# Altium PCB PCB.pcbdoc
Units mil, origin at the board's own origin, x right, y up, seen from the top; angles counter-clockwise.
Board outline 4135 x 3135 mil, 2 copper layers (Top Layer, Bottom Layer); 52 components, 91 nets, 233 pads, 32 vias.
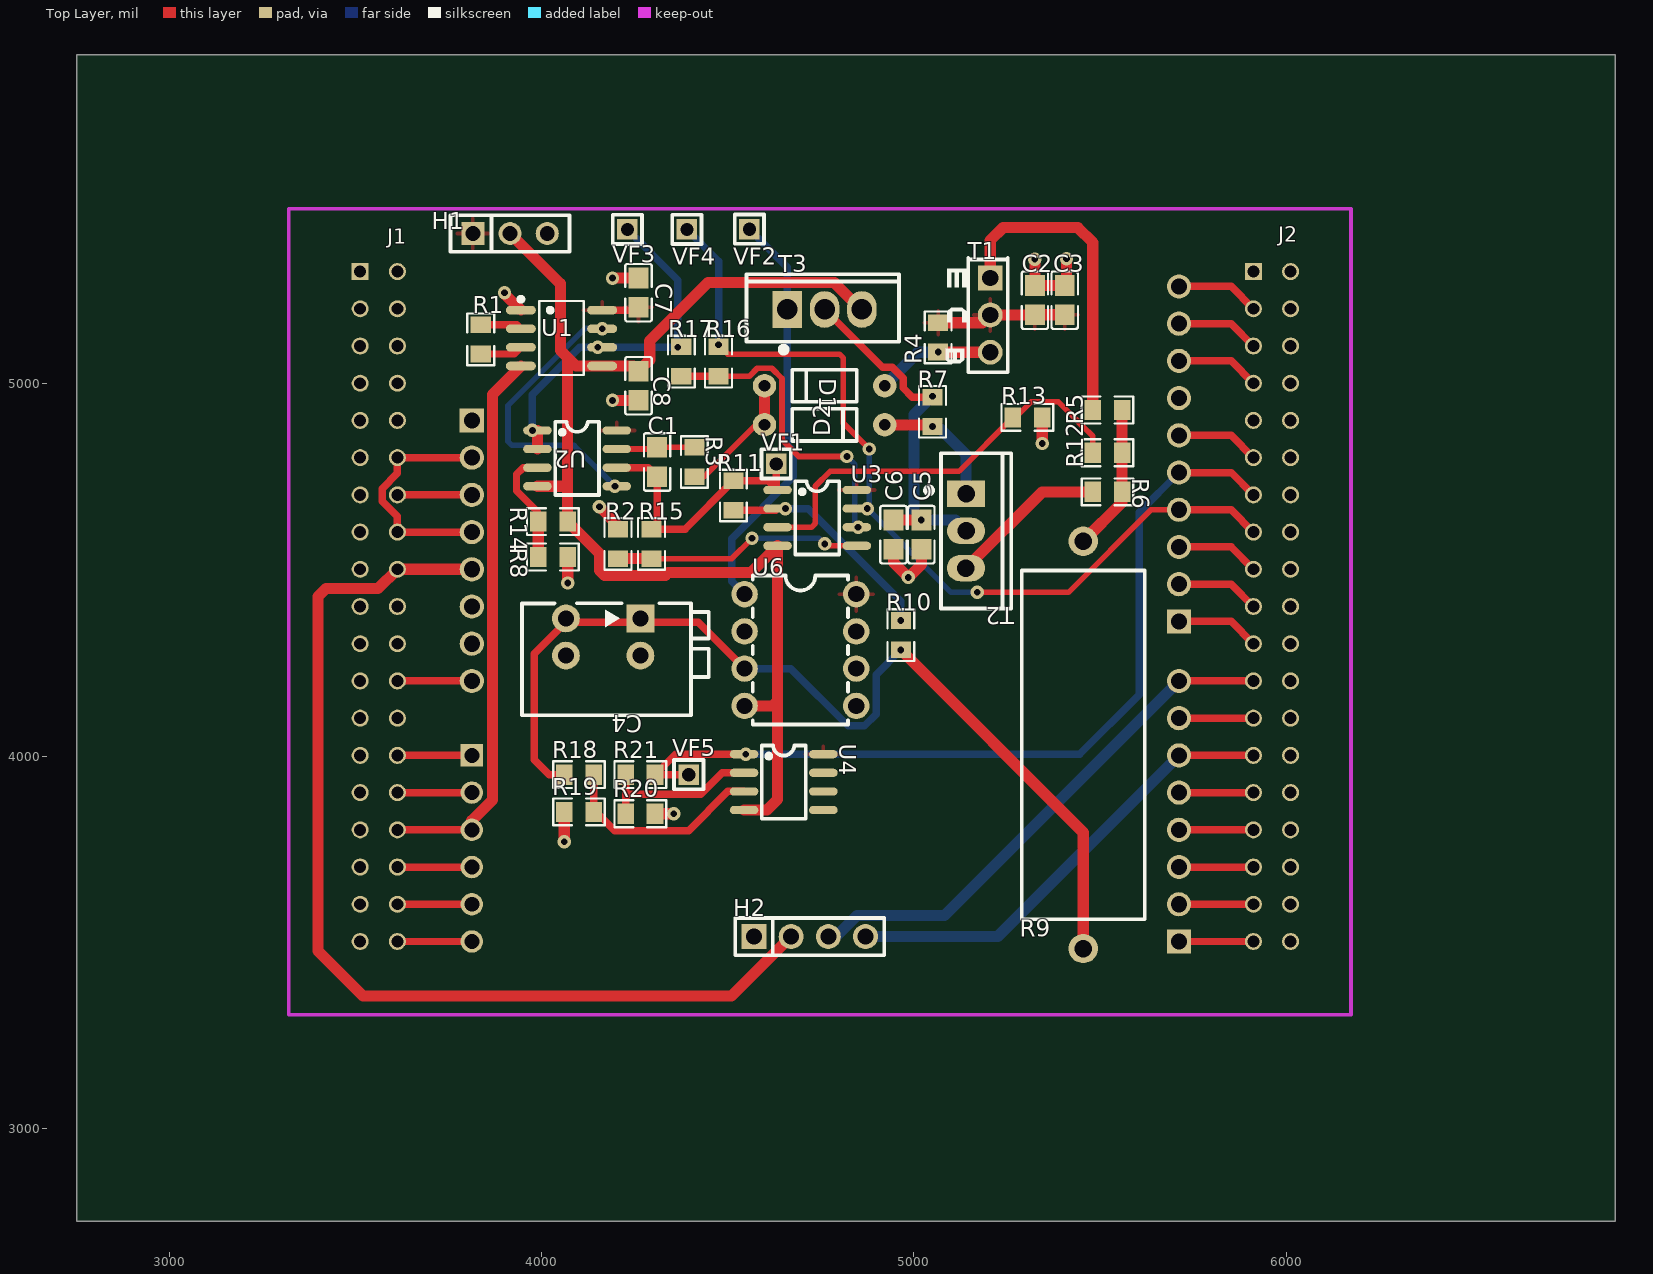
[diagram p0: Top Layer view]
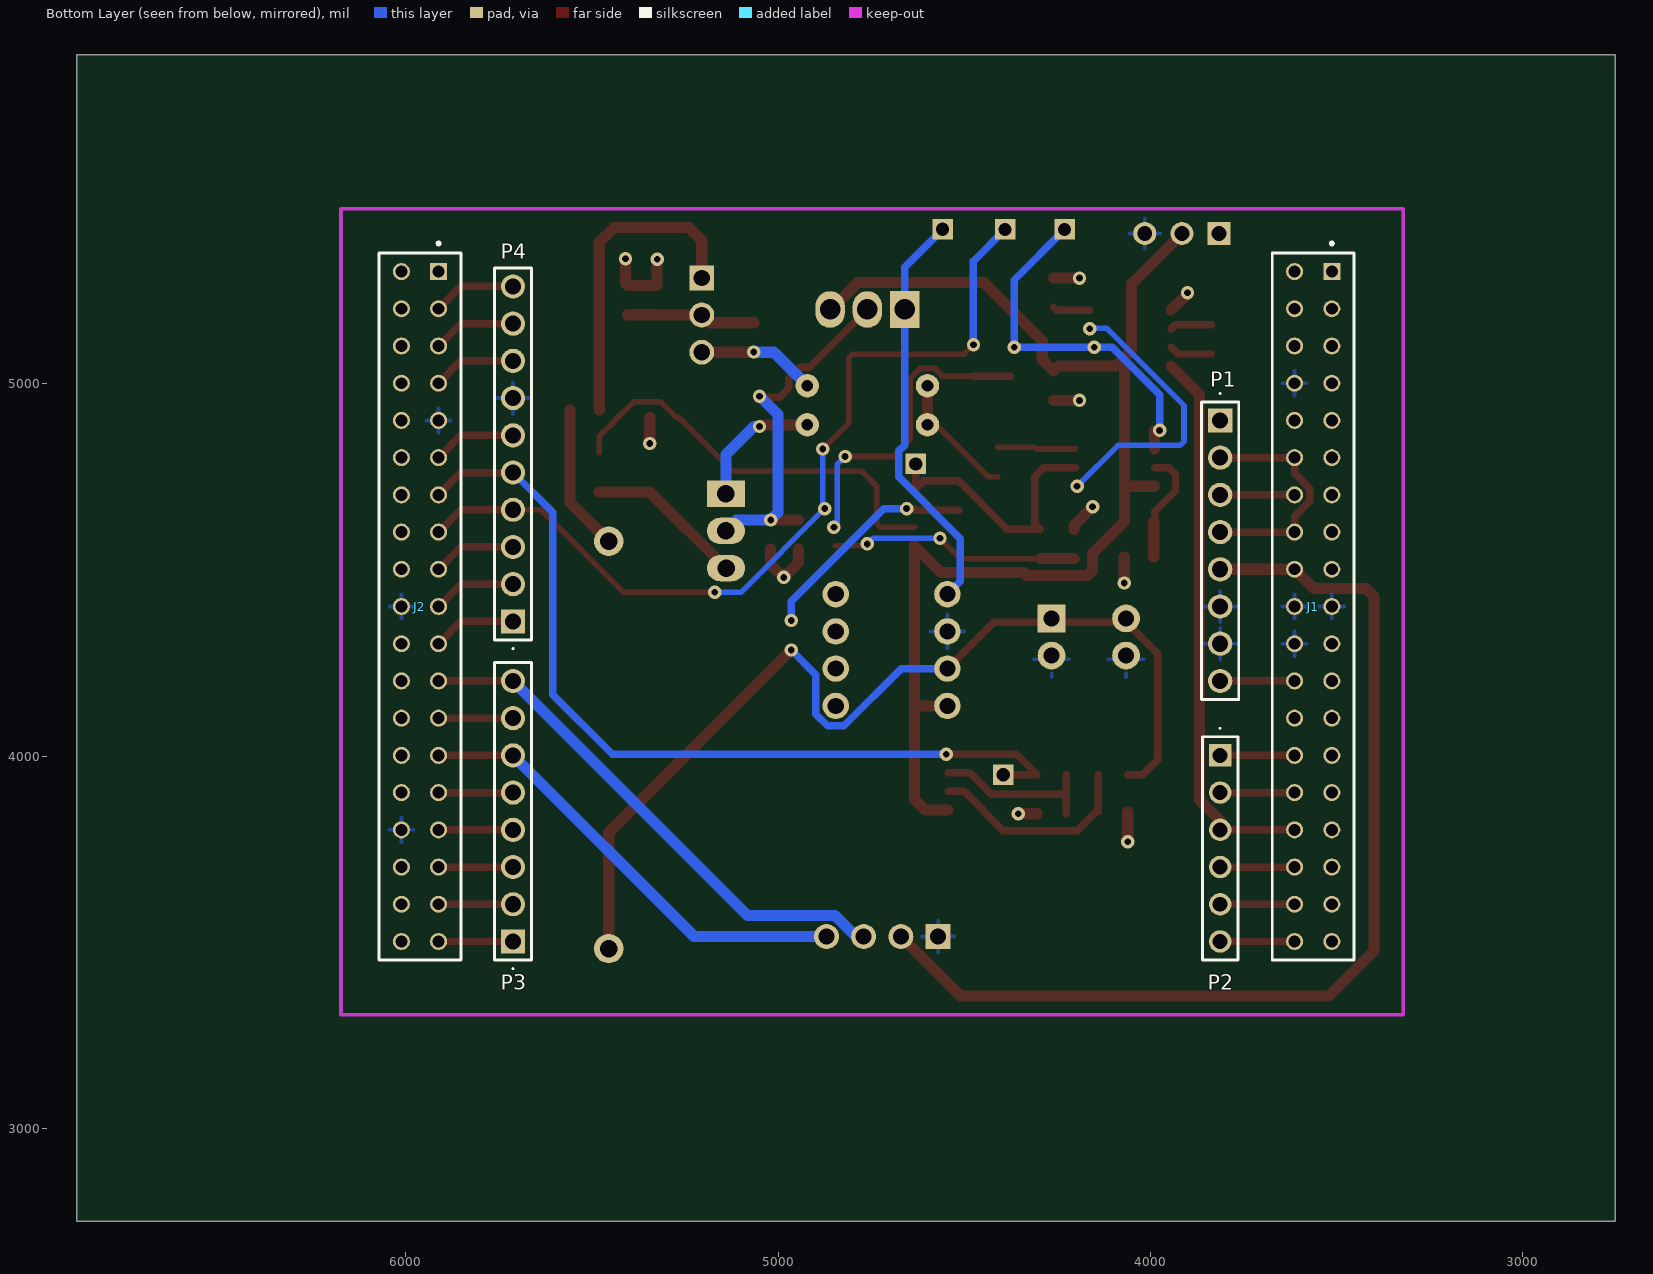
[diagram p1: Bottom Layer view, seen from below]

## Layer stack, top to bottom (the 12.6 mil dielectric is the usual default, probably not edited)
Top Layer: signal copper (thickness not stored)
Dielectric: dielectric 12.6, FR-4, Dk 4.8
Bottom Layer: signal copper (thickness not stored)

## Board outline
6885,2750 2750,2750 2750,5885 6885,5885

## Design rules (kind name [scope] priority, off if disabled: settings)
BoardOutlineClearance safeClearance [All] p0: genericclearance=10 ignorepadtopadclearanceinfootprint=FALSE except(0: Arc-SplitContinuation Track-SplitContinuation SMDPad-SplitContinuation THPad-SplitContinuation Via-SplitContinuation Fill-SplitContinuation Poly-SplitContinuation Region-SplitContinuation Text-SplitContinuation; 8: Track-CutoutEdge SMDPad-CutoutEdge THPad-CutoutEdge Via-CutoutEdge Fill-CutoutEdge Region-CutoutEdge; 11.8: Track-OutlineEdge SMDPad-OutlineEdge THPad-OutlineEdge Via-OutlineEdge Fill-OutlineEdge Region-OutlineEdge Poly-OutlineEdge Text-OutlineEdge)
Clearance safeClearance [(InNet('J1') OR InNet('J2') OR InNet('P1') OR InNet('P2') OR InNet('P3') OR InNet('P4') OR InNet('GND') OR InNet('$1N1763') OR InNet('$1N1673') OR InNet('+12V') OR InNet('$1N2775') OR InNet('$1N2265') OR InNet('-12V') OR InNet('$1N2115') OR InNet('$1N2185') OR InNet('$1N2209') OR InNet('$1N1175') OR InNet('$1N1180') OR InNet('$1N3065') OR InNet('$1N3052') OR InNet('$1N2342') OR InNet('$1N2346') OR InNet('$1N2351') OR InNet('$1N1817') OR InNet('$1N2781') OR InNet('$1N2770') OR InNet('$1N1423') OR InNet('$1N2552') OR InNet('$1N1419') OR InNet('PC10') OR InNet('PC11') OR InNet('PC12') OR InNet('PD2') OR InNet('VDD') OR InNet('E5V') OR InNet('BOOT0') OR InNet('PF6') OR InNet('PF7') OR InNet('+3V3') OR InNet('PA13') OR InNet('NRST') OR InNet('PA14') OR InNet('PA15') OR InNet('+5V') OR InNet('PB7') OR InNet('PC13') OR InNet('VIN') OR InNet('PC14') OR InNet('PC15') OR InNet('PA0') OR InNet('PH0') OR InNet('PA1') OR InNet('PH1') OR InNet('PA4') OR InNet('VBAT') OR InNet('PB0') OR InNet('PC2') OR InNet('PC1') OR InNet('PC3') OR InNet('PC0') OR InNet('PA8') OR InNet('PB10') OR InNet('PB4') OR InNet('PB5') OR InNet('PB3') OR InNet('PA10') OR InNet('PA2') OR InNet('PA3') OR InNet('PB8') OR InNet('PB9') OR InNet('AVDD') OR InNet('PA5') OR InNet('PB6') OR InNet('PC7') OR InNet('PA9') OR InNet('PC9') OR InNet('PC8') OR InNet('PC6') OR InNet('PC5') OR InNet('U5V') OR InNet('PD8') OR InNet('PA12') OR InNet('PA11') OR InNet('PB12') OR InNet('PB11') OR InNet('PB2') OR InNet('PB1') OR InNet('PB15') OR InNet('PB14') OR InNet('PB13') OR InNet('PC4') OR InNet('PF5') OR InNet('PF4') OR InNet('$1N5009') OR InNet('$1N5010') OR InNet('PA7') OR InNet('PA6'))] p1: gap=7 ignorepadtopadclearanceinfootprint=FALSE except(6.9: Track-Hole SMDPad-Hole THPad-Hole Via-Hole Fill-Hole Region-Hole Poly-Hole Text-Hole Sheet-Hole; 8: Track-Track Track-SMDPad SMDPad-SMDPad Track-THPad SMDPad-THPad THPad-THPad Track-Via SMDPad-Via THPad-Via Via-Via Track-Fill SMDPad-Fill THPad-Fill Via-Fill Fill-Fill Track-Region SMDPad-Region THPad-Region Via-Region Fill-Region Region-Region Track-Poly SMDPad-Poly THPad-Poly Via-Poly Fill-Poly Region-Poly Poly-Poly Track-Text SMDPad-Text THPad-Text Via-Text Fill-Text Region-Text Poly-Text Text-Text; 11.8: Track-Sheet SMDPad-Sheet THPad-Sheet Via-Sheet Fill-Sheet Region-Sheet Poly-Sheet Text-Sheet)
DiffPairsRouting differentialPair [All] p1: maxuncoupledlength=10 minlimit=6 maxlimit=6 mostfreqgap=6 toplayer_minwidth=5 toplayer_prefwidth=10 toplayer_maxwidth=100 bottomlayer_minwidth=5 bottomlayer_prefwidth=10 bottomlayer_maxwidth=100
PasteMaskExpansion pasteMaskExpansion [All] p1: expansion=0
PlaneConnect innerPlane [All] p1: planeconnectstyle=Relief reliefexpansion=20 reliefentries=4 reliefconductorwidth=10 reliefairgap=10
PolygonConnect copperRegion [All] p1: connectstyle=Relief reliefentries=4 reliefconductorwidth=10 polygonreliefangle="90 Angle" airgapwidth=10
RoutingVias viaSize [All] p1: viastyle="Through Hole" holewidth=12 minholewidth=11.8 maxholewidth=236.2 width=24 minwidth=19.7 maxwidth=393.7
SolderMaskExpansion solderMaskExpansion [All] p1: useseparateexpansions=TRUE expansion=2 expansionbottom=2
Width trackWidth [All] p1: maxlimit=100 minlimit=15 preferedwidth=15

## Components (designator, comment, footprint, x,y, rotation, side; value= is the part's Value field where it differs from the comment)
C1 "CAP_0805" C0805 4310,4790 r90 top
C2 "CAP_0805" C0805 5325,5225 r90 top
C3 "CAP_0805" C0805 5405,5225 r90 top
C4 "KF141V-2.54-2P" CONN-TH_2P-P2.54_KF141V-2.54-2P 4165,4320 r270 top
C5 "CAP_0805" C0805 5020,4595 r270 top
C6 "CAP_0805" C0805 4945,4595 r270 top
C7 "CAP_0805" C0805 4260,5245 r270 top
C8 "CAP_0805" C0805 4260,4995 r90 top
D1 "1N4448TR" DO-35_BD2.0-L4.2-P8.20-D0.5-RD 4760,4995 r0 top
D2 "1N4448TR" DO-35_BD2.0-L4.2-P8.20-D0.5-RD 4760,4890 r180 top
H1 "HDR-F_2.54_1x3P" HDR-TH_3P-P2.54-V-F 3914.84,5404.08 r0 top locked
H2 "PZ254V-11-04P" HDR-TH_4P-P2.54-V-M 4720,3515 r0 top locked
J1 "CES-119-02-T-D" SAMTEC_CES-119-02-T-D 3512.13,5301.85 r90 bottom locked
J2 "CES-119-02-T-D" SAMTEC_CES-119-02-T-D 5912.13,5301.85 r90 bottom locked
P1 "61300811121" HDRV8W64P0X254_1X8_2032X254X854P 3812.13,4901.85 r270 bottom locked
P2 "10129378-906001BLF" 10129378906001BLF 3812.13,4001.85 r270 bottom locked
P3 "61300811121" HDRV8W64P0X254_1X8_2032X254X854P 5712.13,3501.85 r90 bottom locked
P4 "TSW-110-07-G-S" HDRV10W64P0X254_1X10_2540X254X838P 5712.13,4361.85 r90 bottom locked
R1 "Res_0805" R0805 3836.07,5119.71 r90 top
R2 "Res_0805" R0805 4205,4570 r270 top
R3 "Res_0805" R0805 4410,4790 r90 top
R4 "Res_0805" R0805 5065,5125 r90 top
R5 "Res_0805" R0805 5520,4930 r180 top
R6 "Res_0805" R0805 5520,4710 r0 top
R7 "Res_0805" R0805 5050,4925 r270 top
R8 "Res_0805" R0805 4030,4535 r180 top
R9 "15FR100E-T" RES-TH_BD8.4-L23.8-P27.8-D1.0 5455,4030 r90 top
R10 "Res_0805" R0805 4965,4325 r270 top
R11 "Res_0805" R0805 4515,4700 r90 top
R12 "Res_0805" R0805 5520,4815 r180 top
R13 "Res_0805" R0805 5305,4910 r180 top
R14 "Res_0805" R0805 4030,4630 r0 top
R15 "Res_0805" R0805 4295,4570 r270 top
R16 "Res_0805" R0805 4475,5060 r90 top
R17 "Res_0805" R0805 4375,5060 r90 top
R18 "Res_0805" R0805 4100,3950 r0 top
R19 "Res_0805" R0805 4100,3850 r0 top
R20 "Res_0805" R0805 4265,3845 r0 top
R21 "Res_0805" R0805 4265,3950 r0 top
T1 "MJE182G" TO-225-3_L7.6-W2.8-P2.54-L 5205,5185 r270 top
T2 "TIP32AG" TO-220-3_L10.0-W4.5-P2.54-L 5140,4605 r270 top
T3 "IRL540NPBF-VB" TO-220AB-3_L10.4-W4.6-P2.54-L 4760,5200 r0 top
U1 "INA826AID" SOIC-8_L4.9-W3.9-P1.27-LS6.0-BL 4053.13,5123.13 r270 top
U2 "OPA2277UA/2K5" SOIC-8_L5.0-W4.0-P1.27-LS6.0-BL 4095,4800 r270 top
U3 "OPA2277UA/2K5" SOIC-8_L5.0-W4.0-P1.27-LS6.0-BL 4740,4640 r270 top
U4 "OPA2277UA/2K5" SOIC-8_L5.0-W4.0-P1.27-LS6.0-BL 4650,3930 r270 top
U6 "LM358AN/NOPB" PDIP-8_L10.2-W6.5-P2.54-LS7.6-BL 4695,4285 r270 top
VF1 "HDR-M_2.54_1x1P" HDR-TH_1P-V-M_XKB_X4611WV-01I-C28D40 4630,4785 r0 top
VF2 "HDR-M_2.54_1x1P" HDR-TH_1P-V-M_XKB_X4611WV-01I-C28D40 4557.96,5415.75 r0 top
VF3 "HDR-M_2.54_1x1P" HDR-TH_1P-V-M_XKB_X4611WV-01I-C28D40 4230,5415 r0 top
VF4 "HDR-M_2.54_1x1P" HDR-TH_1P-V-M_XKB_X4611WV-01I-C28D40 4390,5415 r0 top
VF5 "HDR-M_2.54_1x1P" HDR-TH_1P-V-M_XKB_X4611WV-01I-C28D40 4395,3950 r0 top

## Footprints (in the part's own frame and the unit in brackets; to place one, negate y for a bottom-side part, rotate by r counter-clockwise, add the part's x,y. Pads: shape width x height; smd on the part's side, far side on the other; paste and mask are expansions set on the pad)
10129378906001BLF [mm]
  rect 1.53x1.53 hole 1.02: 1(0,0)
  round 1.53 hole 1.02: 2(2.54,0) 3(5.08,0) 4(7.62,0) 5(10.16,0) 6(12.7,0)
  silkscreen extent -1.9,-1.2 13.97,1.2
C0805 [mm]
  rect 1.41x1.35 smd: 1(-1,0) 2(1,0)
  silkscreen extent -1.96,-0.9 1.96,0.9
CONN-TH_2P-P2.54_KF141V-2.54-2P [mm]
  rect 1.9x1.9 hole 1.1: 1(-1.27,2.54)
  round 1.9 hole 1.1 copper offset 0,0: 1(-1.27,-2.54) 2(1.27,2.54) 2(1.27,-2.54)
  silkscreen extent -2.3,-5.54 5.35,7.2
DO-35_BD2.0-L4.2-P8.20-D0.5-RD [mm]
  round 1.6 hole 0.8: 1(-4.1,0) 2(4.1,0)
  silkscreen extent -2.2,-1.1 2.2,1.1
HDR-TH_1P-V-M_XKB_X4611WV-01I-C28D40 [mm]
  rect 1.4x1.4 hole 0.9: 1(0,0)
  silkscreen extent -1,-1 1,1
HDR-TH_3P-P2.54-V-F [mil]
  rect 62x62 hole 40.16: 1(-100,0)
  round 62 hole 40.16: 2(0,0) 3(100,0)
  silkscreen extent -160,-49 160,49
HDR-TH_4P-P2.54-V-M [mm]
  rect 1.7x1.7 hole 1.1: 1(-3.81,0)
  round 1.7 hole 1.1: 2(-1.27,0) 3(1.27,0) 4(3.81,0)
  silkscreen extent -5.08,-1.27 5.08,1.27
HDRV8W64P0X254_1X8_2032X254X854P [mm]
  rect 1.65x1.65 hole 1.1: 1(0,0)
  round 1.65 hole 1.1: 2(2.54,0) 3(5.08,0) 4(7.62,0) 5(10.16,0) 6(12.7,0) 7(15.24,0) 8(17.78,0)
  silkscreen extent -1.9,-1.27 19.05,1.27
HDRV10W64P0X254_1X10_2540X254X838P [mm]
  rect 1.65x1.65 hole 1.1: 1(0,0)
  round 1.65 hole 1.1: 2(2.54,0) 3(5.08,0) 4(7.62,0) 5(10.16,0) 6(12.7,0) 7(15.24,0) 8(17.78,0) 9(20.32,0) 10(22.86,0)
  silkscreen extent -1.9,-1.27 24.13,1.27
PDIP-8_L10.2-W6.5-P2.54-LS7.6-BL [mm]
  round 1.8 hole 1.1: 1(-3.81,-3.81) 2(-1.27,-3.81) 3(1.27,-3.81) 4(3.81,-3.81) 5(3.81,3.81) 6(1.27,3.81) 7(-1.27,3.81) 8(-3.81,3.81)
  silkscreen extent -5.08,-3.25 5.08,3.25
R0805 [mm]
  rect 1.133x1.377 smd: 1(-1,0) 2(1,0)
  silkscreen extent -1.76,-0.92 1.76,0.92
RES-TH_BD8.4-L23.8-P27.8-D1.0 [mm]
  round 2 hole 1.2: 1(-13.9,0) 2(13.9,0)
  silkscreen extent -11.9,-4.2 11.9,4.2
SAMTEC_CES-119-02-T-D [mm]
  rect 1.16x1.16 hole 0.81: 1(0,0)
  round 1.16 hole 0.81: 2(0,2.54) 3(-2.54,0) 4(-2.54,2.54) 5(-5.08,0) 6(-5.08,2.54) 7(-7.62,0) 8(-7.62,2.54) 9(-10.16,0) 10(-10.16,2.54) 11(-12.7,0) 12(-12.7,2.54) 13(-15.24,0) 14(-15.24,2.54) 15(-17.78,0) 16(-17.78,2.54) 17(-20.32,0) 18(-20.32,2.54) 19(-22.86,0) 20(-22.86,2.54) 21(-25.4,0) 22(-25.4,2.54) 23(-27.94,0) 24(-27.94,2.54) 25(-30.48,0) 26(-30.48,2.54) 27(-33.02,0) 28(-33.02,2.54) 29(-35.56,0) 30(-35.56,2.54) 31(-38.1,0) 32(-38.1,2.54) 33(-40.64,0) 34(-40.64,2.54) 35(-43.18,0) 36(-43.18,2.54) 37(-45.72,0) 38(-45.72,2.54)
  silkscreen extent -46.99,-1.53 2.02,4.07
SOIC-8_L4.9-W3.9-P1.27-LS6.0-BL [mm]
  oval 0.588x2.045 smd: 1(-1.905,-2.772) 2(-0.635,-2.772) 3(0.635,-2.772) 4(1.905,-2.772) 5(1.905,2.772) 6(0.635,2.772) 7(-0.635,2.772) 8(-1.905,2.772)
  silkscreen extent -2.8,-2.92 2.53,1.52
SOIC-8_L5.0-W4.0-P1.27-LS6.0-BL [mil]
  oval 22.38x76.78 smd: 1(-75,-106.5) 2(-25,-106.5) 3(25,-106.5) 4(75,-106.5) 5(75,106.5) 6(25,106.5) 7(-25,106.5) 8(-75,106.5)
  silkscreen extent -98,-59 98,59
TO-220-3_L10.0-W4.5-P2.54-L [mm]
  rect 1.8x2.6 hole 1.2: 1(-2.54,0.005)
  oval 1.8x2.6 hole 1.2: 2(0,0.005)
  oval 1.8x2.6 hole 1.2 copper offset 0,0: 3(2.54,-0.005)
  silkscreen extent -5.3,-2.73 5.3,3.09
TO-220AB-3_L10.4-W4.6-P2.54-L [mm]
  rect 2x2.5 hole 1.4: 1(-2.54,0)
  oval 2x2.5 hole 1.4: 2(0,0) 3(2.54,0)
  silkscreen extent -5.33,-2.94 5.08,2.4
TO-225-3_L7.6-W2.8-P2.54-L [mm]
  rect 1.7x1.7 hole 1.1: 1(-2.54,0)
  round 1.7 hole 1.1: 2(0,0) 3(2.54,0)
  silkscreen extent -3.9,-3.05 3.9,1.2

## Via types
v1: diameter 36, hole 18, Top Layer to Bottom Layer, 32 vias

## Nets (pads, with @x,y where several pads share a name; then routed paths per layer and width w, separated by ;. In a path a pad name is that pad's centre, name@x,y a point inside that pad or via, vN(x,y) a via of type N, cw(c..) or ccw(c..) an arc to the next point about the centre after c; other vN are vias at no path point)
$1N1175: R1.2 U1.2 | length 112.4
  Top Layer w20: R1.2 3933.02,5159.08 U1.2
$1N1180: R1.1 U1.3 | length 115.3
  Top Layer w20: R1.1 3926.19,5080.34 U1.3
$1N1419: U1.7 U2.5 | length 773.1
  Bottom Layer w15: v1(4162.28,5148.13) 4160.4,5150 4117.94,5150 3909.39,4941.46 3909.39,4845.61 3920,4835 4086.67,4835 v1(4196.67,4725)
$1N1423: R17.2 U1.6 U2.1 U2.2 VF3.1 | length 976.1
  Top Layer w20: v1(3975,4875) U2.1
  Top Layer w30: U2.2 U2.1
  Bottom Layer w20: v1(3975,4875) 3975,4971 4102.13,5098.13 v1(4150.82,5098.13) v1(4365.82,5098.13) 4365.82,5279.18 VF3.1
$1N1673: C1.1 R11.2 R15.1 U2.6 U3.1 VF1.1 | length 735
  Top Layer w20: U2.6 4285.63,4775 C1.1 4310,4624.37 R15.1 4385,4609.37 R11.2 4609.13,4739.37 U3.1@4630,4718.5 ; VF1.1 U3.1@4630,4718.5 ; U3.1 U3.1@4630,4718.5
$1N1763: C1.2 R3.2 U2.7 | length 210.3
  Top Layer w15: U2.7 4305.63,4825 C1.2 R3.2
$1N1817: R8.2 R14.1 U2.3 | length 310.2
  Top Layer w20: U2.3 3950,4775 3932.11,4757.11 3932.11,4712.91 3988.5,4656.52 3988.5,4632.13 R14.1
  Top Layer w30: R8.2 R14.1
$1N2115: D1.2 R4.1 T1.3 | length 316.1
  Top Layer w30: v1(5065,5085.63) 5065.63,5085 T1.3
  Bottom Layer w30: D1.2 5011.42,5085 v1@5060,5085
$1N2185: D1.1 D2.2 R3.1 | length 351.3
  Top Layer w15: R3.1 4435.63,4750.63 4575,4890 D2.2
  Top Layer w30: D2.2 D1.1
$1N2209: D2.1 R7.2 T2.1 | length 341.5
  Top Layer w30: D2.1 5045.63,4890 v1(5050,4885.63)
  Bottom Layer w30: v1@5065,4885 5140.19,4809.81 T2.1
$1N2265: C5.1 C6.1 R7.1 T2.2 T3.2 | length 972.3
  Top Layer w20: T3.2 4915.5,5044.5 4941.92,5044.5 4970.92,5015.5 4970.92,4989.08 4995.63,4964.37 R7.1
  Top Layer w30: C6.1 v1(5020,4634.37)
  Bottom Layer w30: v1(5050,4967.22) 5000,4917.23 5000,4654.37 v1(5020,4634.37) 5110.83,4634.37 T2.2
$1N2342: R5.2 T1.1 | length 856.3
  Top Layer w30: T1.1 5205,5385 5240,5420 5440,5420 5480.63,5379.37 R5.2
$1N2346: R5.1 R6.2 R9.2 R12.1 | length 396
  Top Layer w30: R9.2 5559.37,4681.61 R6.2 R12.1 R5.1
$1N2351: R6.1 T2.3 | length 425.7
  Top Layer w30: T2.3 5344.81,4710 R6.1
$1N2552: T3.1 U6.1 VF2.1 | length 1112.5
  Bottom Layer w20: U6.1 4510,4470 4510,4584.43 4675.56,4749.99 4675.56,4820.01 4660,4835.57 T3.1 4660,5313.72 VF2.1
$1N2770: R12.2 R13.2 U3.3 | length 1129.4
  Top Layer w15: U3.3 4708.79,4615 4709.39,4614.39 4724.39,4614.39 4735,4625 4735,4725 4775,4765 5120.63,4765 R13.2 5273.05,4910 5315.66,4952.61 5387.39,4952.61 5442.84,4897.16 5442.84,4896.47 5451.92,4887.39 5452.61,4887.39 5480.63,4859.37 R12.2
$1N2775: C4.1 R9.1 R10.2 R18.1 U6.3 | length 2669
  Top Layer w20: R18.1 4020,3950 3980,3990 3980,4275 4065,4360 4264.98,4360 4420.01,4359.99 U6.3
  Top Layer w30: v1(4965,4285) 5455,3795 R9.1
  Bottom Layer w20: U6.3 4669.43,4235 4822.87,4081.57 4867.13,4081.57 4898.43,4112.87 4898.43,4218.43 v1(4965,4285)
$1N2781: R10.1 R11.1 U3.2 | length 579.6
  Top Layer w20: R11.1 4629.13,4660.63 U3.2
  Bottom Layer w20: v1(4654.76,4665) 4715.91,4665 4965,4415.91 v1@4965,4370
  other v1: 4965,4364.37
$1N3052: R16.1 R17.1 U3.6 | length 850.8
  Top Layer w15: R16.1 4557.75,5020.63 4579.11,5042 4618.05,5042 4645.58,5014.47 4645.58,4850.05 4690.63,4805 v1(4820,4805)
  Top Layer w20: R17.1 R16.1
  Bottom Layer w15: v1(4820,4805) 4841.5,4783.5 4841.5,4623.5 v1(4850,4615)
$1N3065: R2.2 R15.2 U3.5 | length 672.3
  Top Layer w15: R15.2 4510.63,4530.63 v1(4565,4585) ; v1(4760,4570) 4765,4565 U3.5
  Top Layer w30: R2.2 R15.2
  Bottom Layer w15: v1(4565,4585) 4745,4585 v1(4760,4570)
$1N5009: R18.2 R19.2 U4.3 | length 568.4
  Top Layer w20: R18.2 R19.2 4145.77,3850 4195.88,3799.89 4394.89,3799.89 4500,3905 U4.3
$1N5010: R20.1 R21.1 U4.2 | length 446.8
  Top Layer w20: R20.1 4225.63,3897.29 ; R21.1 4225.63,3897.29 ; U4.2 4485,3955 4427.29,3897.29 4225.63,3897.29
+3V3: J1.12 J1.16 P1.2 P1.4 | length 633.8
  Top Layer w20: P1.4 J1.16 3612.13,4644.1 3571.29,4684.94 3571.29,4718.76 3612.13,4759.6 J1.12 P1.2
+5V: H2.2 J1.18 P1.5 | length 2783.9
  Top Layer w30: P1.5 J1.18 3560.28,4450 3420,4450 3398.79,4428.79 3398.79,3476.21 3520,3355 4510,3355 H2.2
+12V: C2.1 C3.1 C7.2 H1.1 R4.2 T1.2 U1.8 U2.8 U3.8 U4.8 U6.8 | length 449.6
  Top Layer w20: U1.8 4252.5,5198.13 C7.2
  Top Layer w30: R4.2 5184.37,5164.37 T1.2 5324.37,5185 C2.1 C3.1
-12V: C8.2 H1.2 R14.2 T3.3 U1.5 U2.4 U3.4 U4.4 U6.4 | length 3443.7
  Top Layer w30: H1.2 4050,5268.92 4050,5090 4069.37,5070.63 ; U2.4 3988.64,4725.14 4069.37,4725.14 ; U4.4 4605,3855 4633.5,3883.5 4633.5,4147.98 ; U6.4 4620.52,4135 4633.5,4147.98 ; T3.3 4858.05,5200 4785.83,5272.21 4447.21,5272.21 4290,5115 4290,5064.37 C8.2 4246.24,5048.13 U1.5 4091.87,5048.13 4069.37,5070.63 ; 4069.37,4725.14 R14.2 4154.89,4544.48 4154.89,4498.81 4168.37,4485.34 4331.63,4485.34 4339.73,4493.43 4561.93,4493.43 U3.4 4633.5,4147.98 ; 4069.37,4725.14 4069.37,5070.63
AVDD: J2.7 P4.8 | length 224.9
  Top Layer w20: P4.8 5852.13,5061.85 J2.7
BOOT0: J1.7
E5V: J1.6
GND: C2.2 C3.2 C4.2 C5.2 C6.2 C7.1 C8.1 H1.3 H2.1 J1.8 J1.19 J1.20 J1.22 J2.9 J2.20 J2.32 P1.6 P1.7 P4.7 R2.1 R8.1 R13.1 R19.1 R20.2 U1.1 U6.2 | length 944.1
  Top Layer w30: v1(3900,5245) 3900,5242.1 U1.1 ; v1(4060.63,3770) R19.1 ; R8.1 4070,4534.37 v1@4070,4475 ; v1(4155,4670) 4205,4620 R2.1 ; v1(4190,4955.63) C8.1 ; v1(4190,5284.37) C7.1 ; R20.2 v1(4355,3845) ; C6.2 4945,4520 v1(4985,4480) 5020,4515 C5.2 ; v1(5325,5335) C2.2 C3.2 5410,5269.37 v1(5410,5335.9) ; R13.1 5345,4909.37 v1@5345,4850
  other v1: 4070,4465 5345,4840
NRST: J1.14 P1.3 | length 200
  Top Layer w20: J1.14 P1.3
PA0: J1.28 P2.1 | length 200
  Top Layer w20: J1.28 P2.1
PA1: J1.30 P2.2 | length 200
  Top Layer w20: J1.30 P2.2
PA2: J2.35 P3.2 | length 200
  Top Layer w20: P3.2 J2.35
PA3: J2.37 P3.1 | length 200
  Top Layer w20: P3.1 J2.37
PA4: J1.32 P2.3 U1.4 | length 1500.9
  Top Layer w20: J1.32 P2.3
  Top Layer w30: P2.3 3812.13,3826.73 3867.61,3882.21 3867.61,4971.76 U1.4
PA5: J2.11 P4.6 | length 224.9
  Top Layer w20: P4.6 5852.13,4861.85 J2.11
PA6: J2.13 P4.5 R21.2 U4.1 VF5.1 | length 2341.6
  Top Layer w20: VF5.1 R21.2 4359.37,4005 U4.1 ; P4.5 5852.13,4761.85 J2.13
  Bottom Layer w20: v1(4548.33,4005) 5445,4005 5605,4165 5605,4654.72 P4.5
PA7: J2.15 P4.4 R16.2 U3.7 VF4.1 | length 2377.8
  Top Layer w15: v1(4475,5105) 4500,5080 4800,5080 4810.61,5069.39 4810.61,4894.39 v1(4880,4825) ; v1(5170,4440) 5415,4440 5636.85,4661.85 P4.4
  Top Layer w20: P4.4 5852.13,4661.85 J2.15
  Bottom Layer w15: v1(4880,4825) 4880,4670 v1(4875,4665) 5100,4440 v1(5170,4440)
  Bottom Layer w20: VF4.1 4475,5330 v1(4475,5105)
PA8: H2.3 J2.23 P3.8 | length 1426.6
  Top Layer w20: P3.8 J2.23
  Bottom Layer w30: H2.3 4790.15,3515 4846.61,3571.46 5081.74,3571.46 P3.8
PA9: J2.21 P4.1 | length 224.9
  Top Layer w20: P4.1 5852.13,4361.85 J2.21
PA10: J2.33 P3.3 | length 200
  Top Layer w20: P3.3 J2.33
PA11: J2.14
PA12: J2.12
PA13: J1.13
PA14: J1.15
PA15: J1.17
PB0: J1.34 P2.4 | length 200
  Top Layer w20: J1.34 P2.4
PB1: J2.24
PB2: J2.22
PB3: J2.31 P3.4 | length 200
  Top Layer w20: P3.4 J2.31
PB4: H2.4 J2.27 P3.6 | length 1243.8
  Top Layer w20: P3.6 J2.27
  Bottom Layer w30: H2.4 5225.28,3515 P3.6
PB5: J2.29 P3.5 | length 200
  Top Layer w20: P3.5 J2.29
PB6: J2.17 P4.3 | length 224.9
  Top Layer w20: P4.3 5852.13,4561.85 J2.17
PB7: J1.21
PB8: J2.3 P4.10 | length 224.9
  Top Layer w20: P4.10 5852.13,5261.85 J2.3
PB9: J2.5 P4.9 | length 224.9
  Top Layer w20: P4.9 5852.13,5161.85 J2.5
PB10: J2.25 P3.7 | length 200
  Top Layer w20: P3.7 J2.25
PB11: J2.18
PB12: J2.16
PB13: J2.30
PB14: J2.28
PB15: J2.26
PC0: J1.38 P2.6 | length 200
  Top Layer w20: J1.38 P2.6
PC1: J1.36 P2.5 | length 200
  Top Layer w20: J1.36 P2.5
PC2: J1.35
PC3: J1.37
PC4: J2.34
PC5: J2.6
PC6: J2.4
PC7: J2.19 P4.2 | length 224.9
  Top Layer w20: P4.2 5852.13,4461.85 J2.19
PC8: J2.2
PC9: J2.1
PC10: J1.1
PC11: J1.2
PC12: J1.3
PC13: J1.23
PC14: J1.25
PC15: J1.27
PD2: J1.4
PD8: J2.10
PF4: J2.38
PF5: J2.36
PF6: J1.9
PF7: J1.11
PH0: J1.29
PH1: J1.31
U5V: J2.8
VBAT: J1.33
VDD: J1.5
VIN: J1.24 P1.8 | length 200
  Top Layer w20: J1.24 P1.8
pads on no net: J1.10 J1.26 P1.1 U4.5 U4.6 U4.7 U6.5 U6.6 U6.7

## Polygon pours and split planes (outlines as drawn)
+12V on Top Layer (solid, remove dead copper, pour order 0): 3075,5555 6445,5555 6540,5460 6540,3155 6385,3000 3245,3000 3075,3170
GND on Bottom Layer (solid, remove dead copper, pour order 2): 3065,5635 6450,5635 6635,5450 6635,3035 6605,3005 3020,3005 3000,3025 3000,5570

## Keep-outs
Board Outline Layer:
  lines w10: 3320,3305 6174.33,3305 ; 3320,3305 3320,5470.35 ; 3320,3305 6174.33,3305 ; 3320,3305 3320,5470.35 ; 3320,5470.35 6174.33,5470.35 ; 3320,5470.35 6174.33,5470.35 ; 6174.33,3305 6174.33,5470.35 ; 6174.33,3305 6174.33,5470.35

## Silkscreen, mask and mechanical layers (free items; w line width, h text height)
Mechanical Layer:
  lines w10: 3320,3305 6174.33,3305 ; 3320,3305 3320,5470.35 ; 3320,3305 6174.33,3305 ; 3320,3305 3320,5470.35 ; 3320,5470.35 6174.33,5470.35 ; 3320,5470.35 6174.33,5470.35 ; 6174.33,3305 6174.33,5470.35 ; 6174.33,3305 6174.33,5470.35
